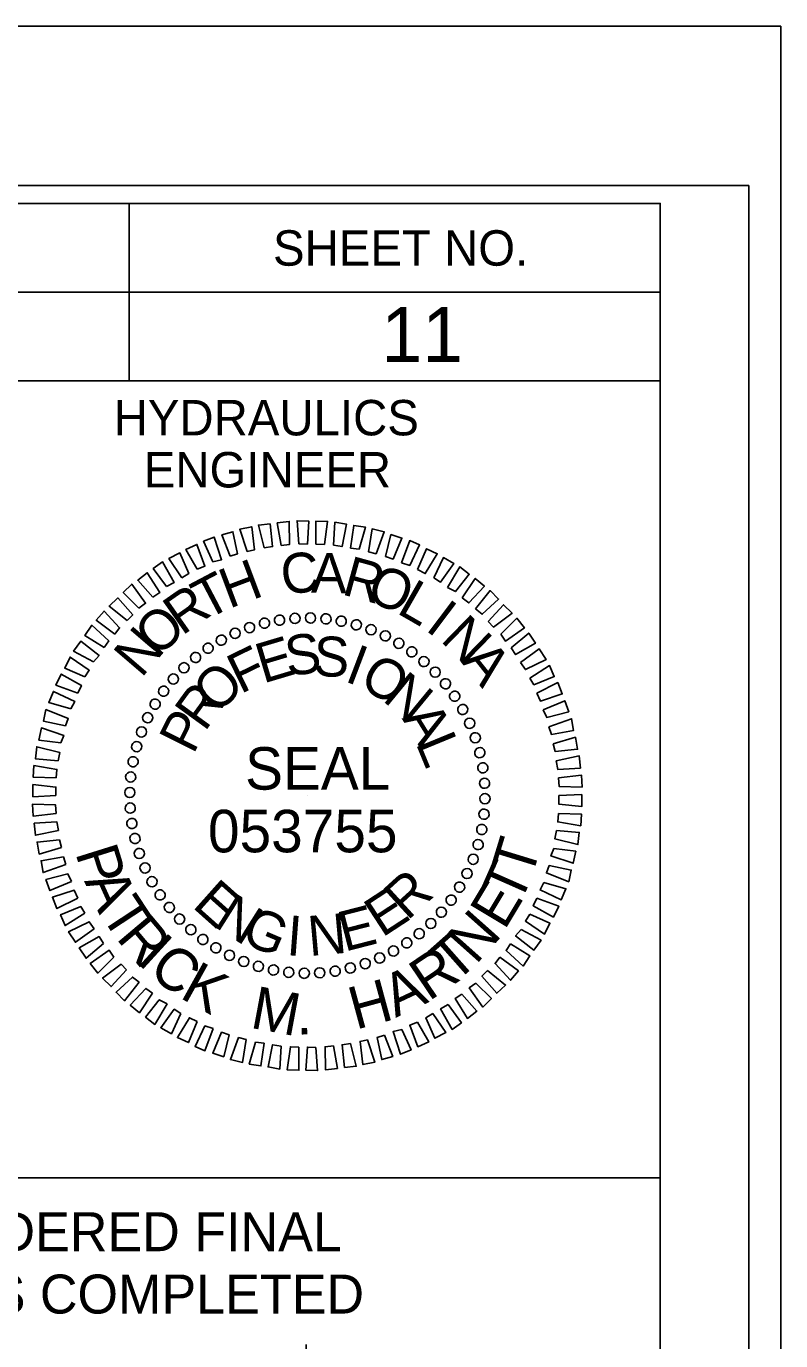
# Model space of a CAD drawing. Extents: x 1629787 to 1631995, y 1166253 to 1167353.
# Drawn here: x 1631364.8 to 1631471.3, y 1167167.9 to 1167353.4 of the extents above; entities that cross this region are included whole.
import ezdxf

# ---------------------------------------------------------------- set-up
doc = ezdxf.new("R2010")
doc.units = 0
for name, color, linetype in [('Sheet Data Field CELL', 7, 'Continuous'), ('Sheet PE Seal Cell', 7, 'Continuous'), ('Sheet Plot Border Inside CELL', 7, 'Continuous'), ('Sheet Plot Border Outside CELL', 7, 'Continuous'), ('Sheet Profile CELL', 7, 'Continuous'), ('Sheet Profile Grid Major CELL', 7, 'Continuous'), ('Sheet Sticker Exception Certification CELL', 7, 'Continuous')]:
    doc.layers.add(name, color=color, linetype=linetype)

msp = doc.modelspace()

# ---------------------------------------------------------------- linework, layer by layer
at = {"layer": 'Sheet PE Seal Cell'}
for p, q in [((1631400.58, 1167269.56), (1631400.58, 1167269.56)), ((1631402.73, 1167269.86), (1631402.73, 1167269.86)), ((1631404.93, 1167269.91), (1631404.93, 1167269.91)), ((1631407.13, 1167269.76), (1631407.13, 1167269.76)), ((1631394.28, 1167267.76), (1631394.28, 1167267.76)), ((1631396.28, 1167268.56), (1631396.28, 1167268.56)), ((1631398.38, 1167269.16), (1631398.38, 1167269.16)), ((1631409.28, 1167269.41), (1631409.28, 1167269.41)), ((1631411.38, 1167268.96), (1631411.38, 1167268.96)), ((1631413.48, 1167268.26), (1631413.48, 1167268.26)), ((1631392.33, 1167266.76), (1631392.33, 1167266.76)), ((1631415.48, 1167267.36), (1631415.48, 1167267.36)), ((1631417.43, 1167266.36), (1631417.43, 1167266.36)), ((1631388.68, 1167264.36), (1631388.68, 1167264.36)), ((1631390.43, 1167265.61), (1631390.43, 1167265.61)), ((1631419.23, 1167265.11), (1631419.23, 1167265.11)), ((1631387.03, 1167262.86), (1631387.03, 1167262.86)), ((1631420.98, 1167263.76), (1631420.98, 1167263.76)), ((1631422.53, 1167262.26), (1631422.53, 1167262.26)), ((1631385.53, 1167261.31), (1631385.53, 1167261.31)), ((1631424.03, 1167260.61), (1631424.03, 1167260.61)), ((1631384.18, 1167259.56), (1631384.18, 1167259.56)), ((1631425.28, 1167258.86), (1631425.28, 1167258.86)), ((1631382.93, 1167257.76), (1631382.93, 1167257.76)), ((1631426.43, 1167256.96), (1631426.43, 1167256.96)), ((1631381.93, 1167255.81), (1631381.93, 1167255.81)), ((1631427.43, 1167255.01), (1631427.43, 1167255.01)), ((1631381.03, 1167253.81), (1631381.03, 1167253.81)), ((1631428.23, 1167253.01), (1631428.23, 1167253.01)), ((1631380.33, 1167251.71), (1631380.33, 1167251.71)), ((1631379.88, 1167249.61), (1631379.88, 1167249.61)), ((1631428.83, 1167250.91), (1631428.83, 1167250.91)), ((1631379.53, 1167247.46), (1631379.53, 1167247.46)), ((1631429.23, 1167248.71), (1631429.23, 1167248.71)), ((1631429.53, 1167246.56), (1631429.53, 1167246.56)), ((1631379.38, 1167245.26), (1631379.38, 1167245.26)), ((1631404.48, 1167244.81), (1631404.48, 1167244.81)), ((1631429.58, 1167244.36), (1631429.58, 1167244.36)), ((1631379.43, 1167243.06), (1631379.43, 1167243.06)), ((1631429.43, 1167242.16), (1631429.43, 1167242.16)), ((1631379.73, 1167240.91), (1631379.73, 1167240.91)), ((1631429.08, 1167240.01), (1631429.08, 1167240.01)), ((1631380.13, 1167238.71), (1631380.13, 1167238.71)), ((1631380.73, 1167236.61), (1631380.73, 1167236.61)), ((1631428.63, 1167237.91), (1631428.63, 1167237.91)), ((1631381.53, 1167234.61), (1631381.53, 1167234.61)), ((1631427.93, 1167235.81), (1631427.93, 1167235.81)), ((1631382.53, 1167232.66), (1631382.53, 1167232.66)), ((1631427.03, 1167233.81), (1631427.03, 1167233.81)), ((1631383.68, 1167230.76), (1631383.68, 1167230.76)), ((1631426.03, 1167231.86), (1631426.03, 1167231.86)), ((1631384.93, 1167229.01), (1631384.93, 1167229.01)), ((1631424.78, 1167230.06), (1631424.78, 1167230.06)), ((1631386.43, 1167227.36), (1631386.43, 1167227.36)), ((1631423.43, 1167228.31), (1631423.43, 1167228.31)), ((1631387.98, 1167225.86), (1631387.98, 1167225.86)), ((1631420.28, 1167225.26), (1631420.28, 1167225.26)), ((1631421.93, 1167226.76), (1631421.93, 1167226.76)), ((1631389.73, 1167224.51), (1631389.73, 1167224.51)), ((1631391.53, 1167223.26), (1631391.53, 1167223.26)), ((1631418.53, 1167224.01), (1631418.53, 1167224.01)), ((1631393.48, 1167222.26), (1631393.48, 1167222.26)), ((1631395.48, 1167221.36), (1631395.48, 1167221.36)), ((1631414.68, 1167221.86), (1631414.68, 1167221.86)), ((1631416.63, 1167222.86), (1631416.63, 1167222.86)), ((1631397.58, 1167220.66), (1631397.58, 1167220.66)), ((1631399.68, 1167220.21), (1631399.68, 1167220.21)), ((1631401.83, 1167219.86), (1631401.83, 1167219.86)), ((1631404.03, 1167219.71), (1631404.03, 1167219.71)), ((1631406.23, 1167219.76), (1631406.23, 1167219.76)), ((1631408.38, 1167220.06), (1631408.38, 1167220.06)), ((1631410.58, 1167220.46), (1631410.58, 1167220.46)), ((1631412.68, 1167221.06), (1631412.68, 1167221.06))]:
    msp.add_line(p, q, dxfattribs=at)
for points in [[(1631395.98, 1167279.26), (1631394.93, 1167282.41), (1631396.63, 1167282.76), (1631397.03, 1167279.51)], [(1631398.38, 1167279.81), (1631397.58, 1167283.01), (1631399.23, 1167283.16), (1631399.58, 1167279.96)], [(1631400.78, 1167280.11), (1631400.23, 1167283.31), (1631401.93, 1167283.51), (1631401.98, 1167280.26)], [(1631403.28, 1167280.36), (1631403.03, 1167283.61), (1631404.68, 1167283.56), (1631404.48, 1167280.31)], [(1631405.68, 1167280.31), (1631405.68, 1167283.56), (1631407.33, 1167283.51), (1631406.88, 1167280.26)], [(1631408.18, 1167280.16), (1631408.38, 1167283.41), (1631410.03, 1167283.11), (1631409.38, 1167279.96)], [(1631410.58, 1167279.76), (1631411.03, 1167282.96), (1631412.68, 1167282.71), (1631411.78, 1167279.61)], [(1631391.13, 1167277.81), (1631389.83, 1167280.71), (1631391.33, 1167281.31), (1631392.38, 1167278.11)], [(1631393.58, 1167278.61), (1631392.43, 1167281.61), (1631393.98, 1167282.06), (1631394.63, 1167278.96)], [(1631413.13, 1167279.21), (1631413.63, 1167282.46), (1631415.33, 1167282.06), (1631414.18, 1167278.96)], [(1631415.53, 1167278.56), (1631416.28, 1167281.66), (1631417.83, 1167281.16), (1631416.58, 1167278.21)], [(1631417.78, 1167277.66), (1631418.93, 1167280.81), (1631420.33, 1167280.21), (1631418.93, 1167277.31)], [(1631386.78, 1167275.56), (1631384.93, 1167278.26), (1631386.48, 1167279.06), (1631387.73, 1167276.16)], [(1631388.93, 1167276.76), (1631387.33, 1167279.56), (1631388.88, 1167280.26), (1631390.03, 1167277.21)], [(1631420.03, 1167276.71), (1631421.28, 1167279.66), (1631422.83, 1167278.96), (1631421.13, 1167276.16)], [(1631384.58, 1167274.31), (1631382.73, 1167276.86), (1631384.03, 1167277.81), (1631385.68, 1167274.91)], [(1631422.33, 1167275.56), (1631423.68, 1167278.41), (1631425.18, 1167277.56), (1631423.28, 1167274.96)], [(1631424.28, 1167274.21), (1631426.03, 1167277.11), (1631427.33, 1167276.06), (1631425.38, 1167273.61)], [(1631382.68, 1167272.81), (1631380.53, 1167275.21), (1631381.88, 1167276.26), (1631383.63, 1167273.46)], [(1631426.33, 1167272.71), (1631428.18, 1167275.46), (1631429.48, 1167274.36), (1631427.28, 1167272.01)], [(1631380.68, 1167271.26), (1631378.48, 1167273.46), (1631379.68, 1167274.66), (1631381.63, 1167271.96)], [(1631428.23, 1167271.16), (1631430.28, 1167273.76), (1631431.48, 1167272.56), (1631429.18, 1167270.41)], [(1631379.03, 1167269.51), (1631376.48, 1167271.56), (1631377.73, 1167272.71), (1631379.83, 1167270.31)], [(1631430.03, 1167269.41), (1631432.18, 1167271.76), (1631433.38, 1167270.56), (1631430.78, 1167268.61)], [(1631377.28, 1167267.61), (1631374.68, 1167269.56), (1631375.78, 1167270.86), (1631377.98, 1167268.51)], [(1631431.78, 1167267.61), (1631434.08, 1167269.86), (1631435.13, 1167268.51), (1631432.48, 1167266.61)], [(1631375.78, 1167265.71), (1631373.08, 1167267.41), (1631374.03, 1167268.86), (1631376.43, 1167266.66)], [(1631433.28, 1167265.66), (1631435.73, 1167267.76), (1631436.68, 1167266.31), (1631433.88, 1167264.71)], [(1631374.28, 1167263.71), (1631371.48, 1167265.21), (1631372.48, 1167266.61), (1631375.08, 1167264.61)], [(1631373.08, 1167261.56), (1631370.23, 1167262.81), (1631370.98, 1167264.36), (1631373.68, 1167262.51)], [(1631434.58, 1167263.61), (1631437.23, 1167265.51), (1631438.18, 1167264.01), (1631435.28, 1167262.61)], [(1631435.88, 1167261.41), (1631438.68, 1167263.16), (1631439.33, 1167261.61), (1631436.48, 1167260.46)], [(1631372.08, 1167259.26), (1631368.98, 1167260.41), (1631369.73, 1167261.96), (1631372.58, 1167260.36)], [(1631436.88, 1167259.26), (1631439.83, 1167260.76), (1631440.48, 1167259.16), (1631437.38, 1167258.16)], [(1631371.08, 1167257.06), (1631367.98, 1167257.96), (1631368.63, 1167259.51), (1631371.63, 1167258.11)], [(1631370.33, 1167254.66), (1631367.23, 1167255.31), (1631367.58, 1167256.96), (1631370.73, 1167255.71)], [(1631437.78, 1167256.91), (1631440.83, 1167258.21), (1631441.38, 1167256.66), (1631438.28, 1167255.86)], [(1631438.58, 1167254.51), (1631441.78, 1167255.66), (1631442.08, 1167254.01), (1631438.93, 1167253.46)], [(1631369.68, 1167252.26), (1631366.58, 1167252.66), (1631366.93, 1167254.36), (1631370.08, 1167253.31)], [(1631439.18, 1167252.11), (1631442.33, 1167253.06), (1631442.63, 1167251.36), (1631439.48, 1167251.06)], [(1631369.28, 1167249.71), (1631366.08, 1167250.01), (1631366.28, 1167251.71), (1631369.53, 1167250.91)], [(1631439.63, 1167249.71), (1631442.88, 1167250.41), (1631443.03, 1167248.71), (1631439.83, 1167248.51)], [(1631369.03, 1167247.31), (1631365.78, 1167247.41), (1631365.88, 1167249.06), (1631369.13, 1167248.51)], [(1631439.93, 1167247.31), (1631443.18, 1167247.71), (1631443.28, 1167246.01), (1631440.03, 1167246.11)], [(1631368.98, 1167244.81), (1631365.73, 1167244.66), (1631365.73, 1167246.36), (1631368.98, 1167246.01)], [(1631369.03, 1167242.31), (1631365.78, 1167241.91), (1631365.68, 1167243.61), (1631368.93, 1167243.51)], [(1631439.98, 1167244.81), (1631443.23, 1167244.96), (1631443.23, 1167243.26), (1631439.98, 1167243.61)], [(1631439.93, 1167242.31), (1631443.18, 1167242.21), (1631443.08, 1167240.56), (1631439.83, 1167241.11)], [(1631369.33, 1167239.91), (1631366.08, 1167239.21), (1631365.93, 1167240.91), (1631369.13, 1167241.11)], [(1631439.68, 1167239.91), (1631442.88, 1167239.61), (1631442.68, 1167237.91), (1631439.43, 1167238.71)], [(1631369.78, 1167237.51), (1631366.63, 1167236.56), (1631366.33, 1167238.26), (1631369.48, 1167238.56)], [(1631370.38, 1167235.11), (1631367.18, 1167233.96), (1631366.88, 1167235.61), (1631370.03, 1167236.16)], [(1631439.28, 1167237.36), (1631442.38, 1167236.96), (1631442.03, 1167235.26), (1631438.88, 1167236.31)], [(1631438.63, 1167234.96), (1631441.73, 1167234.31), (1631441.38, 1167232.66), (1631438.23, 1167233.91)], [(1631371.18, 1167232.71), (1631368.13, 1167231.41), (1631367.58, 1167232.96), (1631370.68, 1167233.76)], [(1631437.88, 1167232.56), (1631440.98, 1167231.66), (1631440.33, 1167230.11), (1631437.33, 1167231.51)], [(1631372.08, 1167230.36), (1631369.13, 1167228.86), (1631368.48, 1167230.46), (1631371.58, 1167231.46)], [(1631373.08, 1167228.21), (1631370.28, 1167226.46), (1631369.63, 1167228.01), (1631372.48, 1167229.16)], [(1631436.88, 1167230.36), (1631439.98, 1167229.21), (1631439.23, 1167227.66), (1631436.38, 1167229.26)], [(1631374.38, 1167226.01), (1631371.73, 1167224.11), (1631370.78, 1167225.61), (1631373.68, 1167227.01)], [(1631435.88, 1167228.06), (1631438.73, 1167226.81), (1631437.98, 1167225.26), (1631435.28, 1167227.11)], [(1631434.68, 1167225.91), (1631437.48, 1167224.41), (1631436.48, 1167223.01), (1631433.88, 1167225.01)], [(1631375.68, 1167223.96), (1631373.23, 1167221.86), (1631372.28, 1167223.31), (1631375.08, 1167224.91)], [(1631433.18, 1167223.91), (1631435.88, 1167222.21), (1631434.93, 1167220.76), (1631432.53, 1167222.96)], [(1631377.18, 1167222.01), (1631374.88, 1167219.76), (1631373.83, 1167221.11), (1631376.48, 1167223.01)], [(1631431.68, 1167222.01), (1631434.28, 1167220.06), (1631433.18, 1167218.76), (1631430.98, 1167221.11)], [(1631378.93, 1167220.21), (1631376.78, 1167217.86), (1631375.58, 1167219.06), (1631378.18, 1167221.01)], [(1631429.93, 1167220.11), (1631432.48, 1167218.06), (1631431.23, 1167216.91), (1631429.13, 1167219.31)], [(1631380.73, 1167218.46), (1631378.68, 1167215.86), (1631377.48, 1167217.06), (1631379.78, 1167219.21)], [(1631382.63, 1167216.91), (1631380.78, 1167214.16), (1631379.48, 1167215.26), (1631381.68, 1167217.61)], [(1631428.28, 1167218.36), (1631430.48, 1167216.16), (1631429.28, 1167214.96), (1631427.33, 1167217.66)], [(1631384.68, 1167215.41), (1631382.93, 1167212.51), (1631381.63, 1167213.56), (1631383.58, 1167216.01)], [(1631426.28, 1167216.81), (1631428.43, 1167214.41), (1631427.08, 1167213.36), (1631425.33, 1167216.16)], [(1631386.63, 1167214.06), (1631385.28, 1167211.21), (1631383.78, 1167212.06), (1631385.68, 1167214.66)], [(1631422.18, 1167214.06), (1631424.03, 1167211.36), (1631422.48, 1167210.56), (1631421.23, 1167213.46)], [(1631424.38, 1167215.31), (1631426.23, 1167212.76), (1631424.93, 1167211.81), (1631423.28, 1167214.71)], [(1631388.93, 1167212.91), (1631387.68, 1167209.96), (1631386.13, 1167210.66), (1631387.83, 1167213.46)], [(1631391.18, 1167211.96), (1631390.03, 1167208.81), (1631388.63, 1167209.41), (1631390.03, 1167212.31)], [(1631420.03, 1167212.86), (1631421.63, 1167210.06), (1631420.08, 1167209.36), (1631418.93, 1167212.41)], [(1631393.43, 1167211.06), (1631392.68, 1167207.96), (1631391.13, 1167208.46), (1631392.38, 1167211.41)], [(1631395.83, 1167210.41), (1631395.33, 1167207.16), (1631393.63, 1167207.56), (1631394.78, 1167210.66)], [(1631412.98, 1167210.36), (1631414.03, 1167207.21), (1631412.33, 1167206.86), (1631411.93, 1167210.11)], [(1631415.38, 1167211.01), (1631416.53, 1167208.01), (1631414.98, 1167207.56), (1631414.33, 1167210.66)], [(1631417.83, 1167211.81), (1631419.13, 1167208.91), (1631417.63, 1167208.31), (1631416.58, 1167211.51)], [(1631398.38, 1167209.86), (1631397.93, 1167206.66), (1631396.28, 1167206.91), (1631397.18, 1167210.01)], [(1631400.78, 1167209.46), (1631400.58, 1167206.21), (1631398.93, 1167206.51), (1631399.58, 1167209.66)], [(1631403.28, 1167209.31), (1631403.28, 1167206.06), (1631401.63, 1167206.11), (1631402.08, 1167209.36)], [(1631405.68, 1167209.26), (1631405.93, 1167206.01), (1631404.28, 1167206.06), (1631404.48, 1167209.31)], [(1631408.18, 1167209.51), (1631408.73, 1167206.31), (1631407.03, 1167206.11), (1631406.98, 1167209.36)], [(1631410.58, 1167209.81), (1631411.38, 1167206.61), (1631409.73, 1167206.46), (1631409.38, 1167209.66)]]:
    msp.add_lwpolyline(points, close=True, dxfattribs=at)
for centre, major_axis in [((1631398.42, 1167269.15), (-0.174, 0.699)), ((1631400.56, 1167269.59), (-0.113, 0.711)), ((1631402.73, 1167269.83), (-0.05, 0.718)), ((1631404.92, 1167269.89), (0.013, 0.72)), ((1631407.11, 1167269.76), (0.075, 0.716)), ((1631409.27, 1167269.43), (0.137, 0.707)), ((1631411.4, 1167268.92), (0.198, 0.692)), ((1631394.28, 1167267.73), (-0.293, 0.658)), ((1631396.32, 1167268.53), (-0.234, 0.681)), ((1631413.47, 1167268.23), (0.258, 0.672)), ((1631415.48, 1167267.36), (0.316, 0.647)), ((1631390.46, 1167265.61), (-0.403, 0.597)), ((1631392.33, 1167266.75), (-0.349, 0.63)), ((1631417.4, 1167266.31), (0.371, 0.617)), ((1631419.23, 1167265.1), (0.423, 0.582)), ((1631388.7, 1167264.31), (-0.453, 0.56)), ((1631420.94, 1167263.74), (0.472, 0.543)), ((1631387.06, 1167262.86), (-0.5, 0.518)), ((1631422.53, 1167262.24), (0.518, 0.5)), ((1631384.19, 1167259.56), (-0.582, 0.423)), ((1631385.56, 1167261.27), (-0.543, 0.472)), ((1631423.98, 1167260.6), (0.56, 0.453)), ((1631382.99, 1167257.73), (-0.617, 0.371)), ((1631425.28, 1167258.84), (0.597, 0.403)), ((1631381.94, 1167255.81), (-0.647, 0.316)), ((1631426.42, 1167256.97), (0.63, 0.349)), ((1631427.4, 1167255.02), (0.658, 0.293)), ((1631381.07, 1167253.8), (-0.672, 0.258)), ((1631428.2, 1167252.98), (0.681, 0.234)), ((1631380.38, 1167251.73), (-0.692, 0.198)), ((1631428.82, 1167250.88), (0.699, 0.174)), ((1631379.87, 1167249.6), (-0.707, 0.137)), ((1631429.26, 1167248.74), (0.711, 0.113)), ((1631379.54, 1167247.44), (-0.716, 0.075)), ((1631429.5, 1167246.56), (0.718, 0.05)), ((1631379.41, 1167245.25), (-0.72, 0.013)), ((1631379.47, 1167243.06), (-0.718, -0.05)), ((1631429.56, 1167244.38), (0.72, -0.013)), ((1631429.43, 1167242.19), (0.716, -0.075)), ((1631379.71, 1167240.89), (-0.711, -0.113)), ((1631429.1, 1167240.03), (0.707, -0.137)), ((1631380.15, 1167238.75), (-0.699, -0.174)), ((1631428.59, 1167237.9), (0.692, -0.198)), ((1631380.77, 1167236.65), (-0.681, -0.234)), ((1631427.9, 1167235.83), (0.672, -0.258)), ((1631381.57, 1167234.61), (-0.658, -0.293)), ((1631427.03, 1167233.82), (0.647, -0.316)), ((1631382.55, 1167232.66), (-0.63, -0.349)), ((1631425.98, 1167231.9), (0.617, -0.371)), ((1631383.69, 1167230.79), (-0.597, -0.403)), ((1631424.77, 1167230.07), (0.582, -0.423)), ((1631384.99, 1167229.03), (-0.56, -0.453)), ((1631423.41, 1167228.36), (0.543, -0.472)), ((1631386.44, 1167227.39), (-0.518, -0.5)), ((1631421.91, 1167226.77), (0.5, -0.518)), ((1631388.03, 1167225.89), (-0.472, -0.543)), ((1631389.74, 1167224.52), (-0.423, -0.582)), ((1631420.27, 1167225.32), (0.453, -0.56)), ((1631391.57, 1167223.32), (-0.371, -0.617)), ((1631416.64, 1167222.88), (0.349, -0.63)), ((1631418.51, 1167224.02), (0.403, -0.597)), ((1631393.49, 1167222.27), (-0.316, -0.647)), ((1631395.5, 1167221.4), (-0.258, -0.672)), ((1631397.57, 1167220.71), (-0.198, -0.692)), ((1631410.55, 1167220.48), (0.174, -0.699)), ((1631412.65, 1167221.1), (0.234, -0.681)), ((1631414.69, 1167221.9), (0.293, -0.658)), ((1631399.7, 1167220.2), (-0.137, -0.707)), ((1631401.86, 1167219.87), (-0.075, -0.716)), ((1631404.05, 1167219.74), (-0.013, -0.72)), ((1631406.23, 1167219.8), (0.05, -0.718)), ((1631408.41, 1167220.04), (0.113, -0.711))]:
    msp.add_ellipse(centre, major_axis=major_axis, ratio=0.999708, dxfattribs=at)
at = {"layer": 'Sheet Plot Border Inside CELL'}
msp.add_lwpolyline([(1629800.31, 1166275.85), (1631466.81, 1166275.85), (1631466.81, 1167330.95), (1629800.31, 1167330.95)], close=True, dxfattribs=at)
at = {"layer": 'Sheet Plot Border Outside CELL'}
msp.add_lwpolyline([(1629787.31, 1166253.4), (1631471.31, 1166253.4), (1631471.31, 1167353.4), (1629787.31, 1167353.4)], close=True, dxfattribs=at)
at = {"layer": 'Sheet Profile CELL'}
for p, q in [((1631379.31, 1167328.35), (1631379.31, 1167303.35)), ((1631254.26, 1167315.85), (1631454.31, 1167315.85))]:
    msp.add_line(p, q, dxfattribs=at)
for points in [[(1631454.31, 1167328.4), (1629954.31, 1167328.4), (1629954.31, 1166278.4), (1631454.31, 1166278.4)], [(1631254.26, 1167328.4), (1631454.31, 1167328.4), (1631454.31, 1167303.35), (1631254.26, 1167303.35)], [(1631354.31, 1167303.35), (1631454.31, 1167303.35), (1631454.31, 1167190.85), (1631354.31, 1167190.85)]]:
    msp.add_lwpolyline(points, close=True, dxfattribs=at)
at = {"layer": 'Sheet Profile Grid Major CELL'}
msp.add_lwpolyline([(1631404.31, 1167167.35), (1631404.31, 1166828.4), (1631454.31, 1166828.4), (1631454.31, 1167178.4)], dxfattribs=at)
at = {"layer": 'Sheet Sticker Exception Certification CELL'}
for p, q in [((1631254.26, 1167190.85), (1631454.3, 1167190.85)), ((1631454.3, 1167190.84), (1631454.3, 1167167.34))]:
    msp.add_line(p, q, dxfattribs=at)

# ---------------------------------------------------------------- texts
at = {"layer": 'Sheet Data Field CELL'}
msp.add_text('11', height=7.75, rotation=360, dxfattribs=at).set_placement((1631414.94, 1167306.01))
at = {"layer": 'Sheet PE Seal Cell'}
for s, height, rotation, p in [('C', 5.64, 6.2199, (1631401.03, 1167273.16)), ('A', 5.64, 359.0203, (1631404.98, 1167273.46)), ('H', 5.64, 20.6195, (1631393.43, 1167271.16)), ('R', 5.64, 344.6211, (1631409.18, 1167273.26)), ('O', 5.64, 337.4212, (1631412.53, 1167272.51)), ('T', 5.64, 27.8198, (1631390.18, 1167269.51)), ('L', 5.64, 330.2209, (1631416.93, 1167270.66)), ('R', 5.64, 35.0205, (1631386.78, 1167267.31)), ('I', 5.64, 323.0201, (1631420.98, 1167268.26)), ('O', 5.64, 42.2217, (1631383.33, 1167264.21)), ('N', 5.64, 315.8189, (1631423.13, 1167266.71)), ('N', 5.64, 49.4235, (1631381.03, 1167261.31)), ('S', 5.64, 7.2556, (1631401.68, 1167261.66)), ('F', 5.64, 25.967, (1631395.03, 1167259.11)), ('E', 5.64, 16.6111, (1631398.23, 1167260.61)), ('S', 5.64, 357.9004, (1631405.28, 1167261.71)), ('I', 5.64, 339.1896, (1631409.58, 1167261.01)), ('O', 5.64, 329.8335, (1631411.58, 1167260.31)), ('A', 5.64, 308.6172, (1631426.08, 1167263.76)), ('O', 5.64, 44.6812, (1631391.73, 1167256.16)), ('N', 5.64, 320.4766, (1631414.93, 1167258.31)), ('R', 5.64, 54.0397, (1631389.98, 1167253.71)), ('P', 5.64, 63.3989, (1631388.38, 1167250.51)), ('A', 5.64, 301.7603, (1631417.78, 1167255.71)), ('L', 5.64, 292.4009, (1631419.73, 1167252.26)), ('SEAL', 5.998, 360, (1631395.69, 1167245.66)), ('T', 6, 72.9557, (1631436.09, 1167232.94)), ('P', 6, 287.3534, (1631371.69, 1167236.76)), ('T', 6, 66.1555, (1631434.46, 1167229.28)), ('A', 6, 294.4627, (1631372.94, 1167232.76)), ('E', 5.64, 318.2769, (1631388.08, 1167229.16)), ('R', 5.64, 42.4814, (1631418.58, 1167227.06)), ('E', 6, 59.0461, (1631432.31, 1167225.69)), ('T', 6, 303.303, (1631375.17, 1167228.06)), ('N', 5.64, 327.634, (1631391.08, 1167226.46)), ('E', 5.64, 33.1241, (1631415.03, 1167224.71)), ('G', 5.64, 336.9902, (1631394.88, 1167224.21)), ('E', 5.64, 14.4118, (1631409.73, 1167222.76)), ('R', 6, 310.1033, (1631377.36, 1167224.7)), ('I', 5.64, 355.7012, (1631401.43, 1167222.31)), ('N', 5.64, 5.0564, (1631404.78, 1167222.16)), ('N', 6, 48.3203, (1631428.26, 1167220.84)), ('I', 6, 317.5835, (1631380.21, 1167221.34)), ('T', 6, 41.5201, (1631425.26, 1167218.2)), ('C', 6, 321.3855, (1631381.82, 1167219.79)), ('K', 6, 330.9676, (1631386.3, 1167216.36)), ('R', 6, 34.0398, (1631421.62, 1167215.72)), ('A', 6, 25.1995, (1631416.94, 1167213.43)), ('M', 6, 349.4519, (1631396.26, 1167212.07)), ('H', 6, 15.2155, (1631411.31, 1167211.75)), ('.', 6, 0.9814, (1631402.97, 1167211.08))]:
    msp.add_text(s, height=height, rotation=rotation, dxfattribs=at).set_placement(p)
msp.add_text('053755', height=5.998, dxfattribs=at).set_placement((1631390.45, 1167236.81))
at = {"layer": 'Sheet Profile CELL'}
for s, p in [('SHEET NO.', (1631399.63, 1167319.61)), ('HYDRAULICS', (1631377.13, 1167295.66)), ('ENGINEER', (1631381.38, 1167288.31))]:
    msp.add_text(s, height=5, rotation=360, dxfattribs=at).set_placement(p)
at = {"layer": 'Sheet Sticker Exception Certification CELL'}
for s, p in [('DOCUMENT NOT CONSIDERED FINAL', (1631275.33, 1167180.51)), ('UNLESS ALL SIGNATURES COMPLETED', (1631270.26, 1167171.71))]:
    msp.add_text(s, height=5.5, rotation=360, dxfattribs=at).set_placement(p)

doc.saveas('drawing.dxf')
